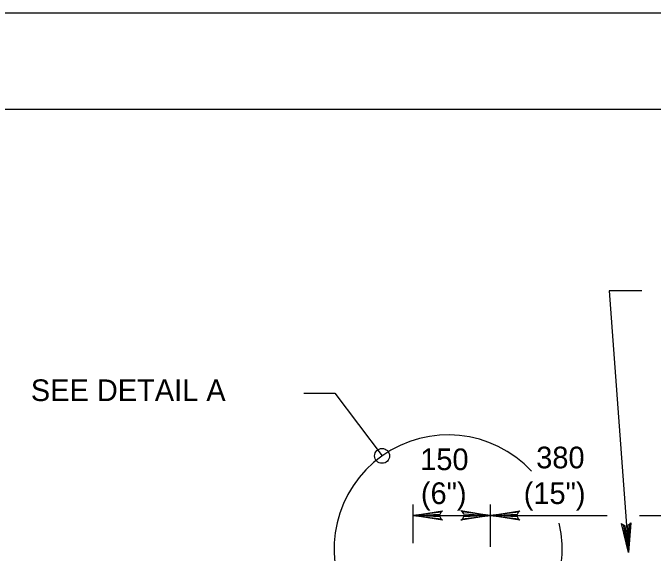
# Model space of a CAD drawing. Extents: x 638447 to 639352, y 298406 to 299000.
# Drawn here: x 638649.1 to 638748.4, y 298916.6 to 299000.5 of the extents above; entities that cross this region are included whole.
import ezdxf

# ---------------------------------------------------------------- set-up
doc = ezdxf.new("R2010")
doc.units = 0
for name, color, linetype in [('1', 7, 'Continuous'), ('2', 7, 'Continuous'), ('3', 7, 'Continuous'), ('PLT-BNDY', 7, 'Continuous')]:
    doc.layers.add(name, color=color, linetype=linetype)

msp = doc.modelspace()

# ---------------------------------------------------------------- linework, layer by layer
at = {"layer": '1'}
msp.add_lwpolyline([(639272.394625, 298421.4725), (639272.394625, 298985.4725), (638486.394625, 298985.4725), (638486.394625, 298421.4725), (639272.394625, 298421.4725), (639272.394625, 298447.8315), (639072.394625, 298447.8315), (639072.394625, 298512.509), (639272.394625, 298512.509), (639272.394625, 298541.4725), (639072.394625, 298541.4725), (639072.394625, 298421.4725), (639151.196125, 298421.4725), (639151.196125, 298447.8315), (639151.196125, 298421.4725), (639228.196125, 298421.4725), (639228.196125, 298447.8315), (639228.196125, 298435.515), (639272.394625, 298435.515)], dxfattribs=at)
msp.add_circle((638706.366591, 298931.729238), 1.154176, dxfattribs=at)
at = {"layer": '2'}
for p, q in [((638746.651125, 298957.3195), (638741.563625, 298957.3195)), ((638741.563625, 298957.3195), (638744.566625, 298916.724)), ((638711.164375, 298918.192), (638711.164375, 298924.178)), ((638723.164375, 298917.634), (638723.164375, 298924.178)), ((638711.164375, 298922.498), (638723.164375, 298922.498)), ((638723.164375, 298922.498), (638741.287875, 298922.498)), ((638746.271125, 298922.498), (638750.650125, 298922.498))]:
    msp.add_line(p, q, dxfattribs=at)
for points in [[(638694.251625, 298941.46125), (638699.051625, 298941.46125), (638706.366625, 298931.72925)], [(638715.524375, 298921.952), (638715.360375, 298922.266), (638711.164375, 298922.498), (638715.524375, 298921.952), (638715.746375, 298921.76), (638711.164375, 298922.498), (638715.358375, 298922.706), (638715.510375, 298923.018), (638711.164375, 298922.498), (638715.746375, 298923.226), (638715.510375, 298923.018)], [(638718.804375, 298923.046), (638718.968375, 298922.73), (638723.164375, 298922.498), (638718.804375, 298923.046), (638718.582375, 298923.236), (638723.164375, 298922.498), (638718.970375, 298922.29), (638718.818375, 298921.978), (638723.164375, 298922.498), (638718.582375, 298921.77), (638718.818375, 298921.978)], [(638727.524375, 298921.952), (638727.360375, 298922.266), (638723.164375, 298922.498), (638727.524375, 298921.952), (638727.746375, 298921.76), (638723.164375, 298922.498), (638727.358375, 298922.706), (638727.510375, 298923.018), (638723.164375, 298922.498), (638727.746375, 298923.226), (638727.510375, 298923.018)], [(638744.790625, 298921.112), (638744.486625, 298920.926), (638744.566625, 298916.724), (638744.790625, 298921.112), (638744.964625, 298921.35), (638744.566625, 298916.724), (638744.050625, 298920.892), (638743.726625, 298921.02), (638744.566625, 298916.724), (638743.502625, 298921.24), (638743.726625, 298921.02)]]:
    msp.add_lwpolyline(points, dxfattribs=at)
msp.add_arc((638716.603191, 298917.290438), 17.699271, 42.96051944, 13.03968056, dxfattribs=at)
at = {"layer": 'PLT-BNDY'}
msp.add_lwpolyline([(638447.394625, 299000.4725), (639288.394625, 299000.4725), (639288.394625, 298406.4725), (638447.394625, 298406.4725)], close=True, dxfattribs=at)

# ---------------------------------------------------------------- texts
at = {"layer": '1'}
for s, p in [('(6")', (638712.382875, 298924.2585)), ('(15")', (638728.328625, 298924.25875))]:
    msp.add_text(s, height=3.36, dxfattribs=at).set_placement(p)
at = {"layer": '3'}
for s, p in [('SEE DETAIL A', (638651.890875, 298940.23325)), ('150', (638712.277625, 298929.51525)), ('380', (638730.269125, 298929.79825))]:
    msp.add_text(s, height=3.36, dxfattribs=at).set_placement(p)

doc.saveas('drawing.dxf')
